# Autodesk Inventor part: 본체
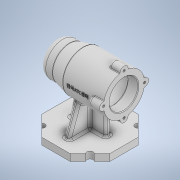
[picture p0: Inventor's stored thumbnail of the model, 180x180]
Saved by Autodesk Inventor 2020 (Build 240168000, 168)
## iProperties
Created: 2021-01
Part Number: 본체
Material: 일반
Document SubType Name: Modeling
Designer: PC2-13
Density: 1 g/cm^3
Appearance: 기본값
Author: PC2-13
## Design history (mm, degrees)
sketch "스케치1"
  geometry: L1 (-50, 50)-(50, 50); L2 (50, 50)-(50, -50); L3 (50, -50)-(-50, -50); L4 (-50, -50)-(-50, 50); L5 (-50, 50)-(50, -50); L6 (50, 50)-(-50, -50); 1 further point
  constraints: 12 end point, 2 midpoint, 2 parallel, 1 horizontal, 1 perpendicular
  dimensions: "d0" = 100 distance of L2.end L3.end; "d1" = 100 distance of L1.end L2.end
extrude "돌출1" new body sketch "스케치1" distance "d2" = 10; taper "d3" = 0 deg
sketch "스케치2"
  geometry: L1 (50, 75)-(-50, 75); L2 (50, 75)-(50, 90); L3 (40, 100)-(30, 100); L4 (-50, 75)-(-50, 105); L5 (-50, 105)-(10, 105); L6 (10, 105)-(30, 100); L7 (-50, 96)-(-35, 96); L8 (-35, 96)-(-35, 99); L9 (-35, 99)-(7, 99); L10 (7, 99)-(7, 96); L11 (7, 96)-(19, 96); L12 (19, 96)-(19, 92.5); L13 (19, 92.5)-(37, 92.5); L14 (37, 92.5)-(37, 91); L15 (37, 91)-(41, 91); L16 (41, 91)-(41, 85.5); L17 (41, 85.5)-(44, 85.5); L18 (44, 85.5)-(44, 75); A1 r 10 centre (40, 90) between (50, 90) and (40, 100); 3 further points
  constraints: 36 end point, 9 perpendicular, 5 vertical, 4 point on line, 2 horizontal, 2 point on circle, 2 tangent, 1 centre point, 1 midpoint, 1 parallel, 1 vertical alignment
  dimensions: "d4" = 100 distance of L1.start L1.end; "d5" = 75 distance from line of point (0, 0) L1; "d6" = 25 distance of L1.start point (50, 100); "d7" = 20 distance of point (50, 100) L3.end; "d8" = 30 distance of L1.end L4.end; "d9" = 60 distance of L4.end L5.end; "d10" = 10 radius of A1; "d11" = 15 distance of L7.start L7.end; "d12" = 42 diameter of L7 L1; "d13" = 42 distance of L8.end L9.end; "d14" = 48 diameter of L9 L1; "d15" = 12 distance of L10.end L11.end; "d16" = 42 diameter of L11 L1; "d17" = 18 distance of L12.end L13.end; "d18" = 35 diameter of L13 L1; "d19" = 4 distance of L14.end L15.end; "d20" = 32 diameter of L15 L1; "d21" = 3 distance of L16.end L17.end; "d22" = 21 diameter of L17 L1
revolve "회전1" sketch "스케치2" stored, may be unused: angle "d23" = 90 deg
fillet "모깎기1" dims "d24" = 3
chamfer "모따기1" distance "d25" = 1; stored, may be unused: second distance "d26" = 2, angle "d27" = 45 deg
fillet "모깎기2" dims "d28" = 0.3
fillet "모깎기3" dims "d29" = 3
fillet "모깎기4" dims "d30" = 3
sketch "스케치3"
  geometry: A1 r 30 centre (0, 0) between (-29.4, -5.97) and (-29.4, 5.97) reference; A2 r 6 centre (-30, 0) between (-29.4, 5.97) and (-29.4, -5.97); 1 further point
  constraints: 4 point on circle, 1 centre point, 1 horizontal alignment
  dimensions: "d32" = 12 diameter of A2; "d33" = 30 distance of A1.centre A2.centre
extrude "돌출2" join sketch "스케치3" distance "d34" = 16; taper "d35" = 0 deg
fillet "모깎기5" dims "d36" = 3
fillet "모깎기6" dims "d37" = 1
sketch "스케치4"
  geometry: A1 r 6 centre (0, 0) between (-0.171, 5.998) and (-0.171, -5.998) reference; 2 further points
  constraints: 1 coincident
hole "구멍1" sketch "스케치4" at (0, 0) diameter "d38" = 3.242; stored, may be unused: countersink angle "d42" = 90 deg, drill point angle "d44" = 118 deg; dims "d39" = 8, "d40" = 4, "d41" = 2, "d43" = 10
sketch "스케치5"
  geometry: L1 (-50, 10)-(50, 10) reference; L2 (-35, 10)-(-19.606, 52.293); L3 (-50, 0)-(-50, 10) reference; L4 (35, 10)-(19.606, 52.293); L5 (50, 0)-(50, 10) reference; L6 (-35, 10)-(35, 10); L7 (-35, 10)-(35, 10); A1 r 30 centre (0, 75) between (-29.226, 68.229) and (-6.771, 45.774) reference; A2 r 30 centre (0, 75) between (6.771, 45.774) and (29.226, 68.229) reference; A3 r 30 centre (0, 75) between (-19.606, 52.293) and (19.606, 52.293); 3 further points
  constraints: 8 end point, 4 point on circle, 2 collinear, 2 point on line, 1 centre point, 1 coincident, 1 concentric
  dimensions: "d48" = 15 distance from line of L3 L2.start; "d49" = 110 deg angle of L2 L1; "d50" = 15 distance from line of L5 L4.start; "d51" = 110 deg angle of L4 L1
extrude "돌출3" join sketch "스케치5" stored distance "d52" = 8; taper "d53" = 0 deg
sketch "스케치7"
  geometry: L1 (-50, 10)-(50, 10) reference; L2 (27, 10)-(23.741, 26.766); 1 further point
  constraints: 2 end point, 1 point on line
  dimensions: "d57" = 23 distance of L2.start L1.end; "d58" = 101 deg angle of L2 L1
feature "리브1" sketch "스케치7" dims "d59" = 1, "d60" = 8, "d61" = 0, "d62" = 0, "d63" = 1, "d64" = 1
sketch "스케치9"
  geometry: L1 (0, 4)-(27, 4); L2 (27, 4)-(27, -4); L3 (27, -4)-(0, -4); L4 (0, -4)-(0, 4); L5 (50, -50)-(50, 50) reference; 2 further points
  constraints: 8 end point, 2 coincident, 2 parallel, 1 horizontal, 1 midpoint, 1 perpendicular
  dimensions: "d68" = 8 distance between parallel lines of L3 L1; "d69" = 23 distance between parallel lines of L5 L2
extrude "돌출6" join sketch "스케치9" stored distance "d70" = 8; taper "d71" = 0 deg
fillet "모깎기7" dims "d72" = 3
fillet "모깎기8" dims "d73" = 3
sketch "스케치10"
  geometry: L1 (-50, 50)-(-50, -50) reference; L2 (50, 50)-(-50, 50) reference; L3 (-50, 20.711)-(-20.711, 50); L4 (-20.711, 50)-(20.711, 50); L5 (20.711, 50)-(50, 20.711); L6 (50, 20.711)-(50, -20.711); L7 (50, -20.711)-(20.711, -50); L8 (20.711, -50)-(-20.711, -50); L9 (-20.711, -50)-(-50, -20.711); L10 (-50, -20.711)-(-50, 20.711); L11 (50, -50)-(-50, -50); L12 (-50, -50)-(-50, 50); L13 (-50, 50)-(50, 50); L14 (50, 50)-(50, -50); L15 (50, -50)-(-50, 50); L16 (-50, -50)-(50, 50); C1 r 50 at (0, 0); 13 further points
  constraints: 28 end point, 4 midpoint, 2 coincident, 2 parallel, 1 centre point, 1 horizontal, 1 perpendicular, 17 other
  dimensions: "d74" = 100 diameter of C1
sketch "스케치11"
  geometry: 1 further point
extrude "돌출7" cut sketch "스케치10" distance "d75" = 43; taper "d76" = 0 deg
sketch "스케치12" dims "d77" = 100
  geometry: L1 (-50, 20.711)-(-20.711, 50) reference; L2 (0, 0)-(-35.355, 35.355); L3 (0, 0)-(0, 50); C1 r 4.5 at (-35.355, 35.355); 1 further point
  constraints: 4 end point, 1 centre point, 1 coincident, 1 midpoint, 1 vertical, 1 vertical alignment, 2 other
  dimensions: "d78" = 9 diameter of C1; "d79" = 45 deg angle of L3 L2 (derived)
extrude "돌출8" cut sketch "스케치12" distance "d80" = 43; taper "d81" = 0 deg
node "작업 평면1"
sketch "스케치13"
  geometry: L1 (50, 105.171)-(50, 111) reference; L2 (50, 69.002)-(50, 80.998) reference; 3 further points
  constraints: 1 horizontal alignment, 1 midpoint, 1 other
  dimensions: "d86" = 38 distance from line of point (12, 75) L1
feature "엠보싱1" sketch "스케치13" dims "d0" = 100, "d1" = 100, "d87" = 0.5, "d88" = 0
node "솔리드1"
pattern_circular "원형 패턴1" dims "d46" = 360 deg
pattern_circular "원형 패턴2" dims angle "d83" = 360 deg
other parameters: "d85" = -74.5
